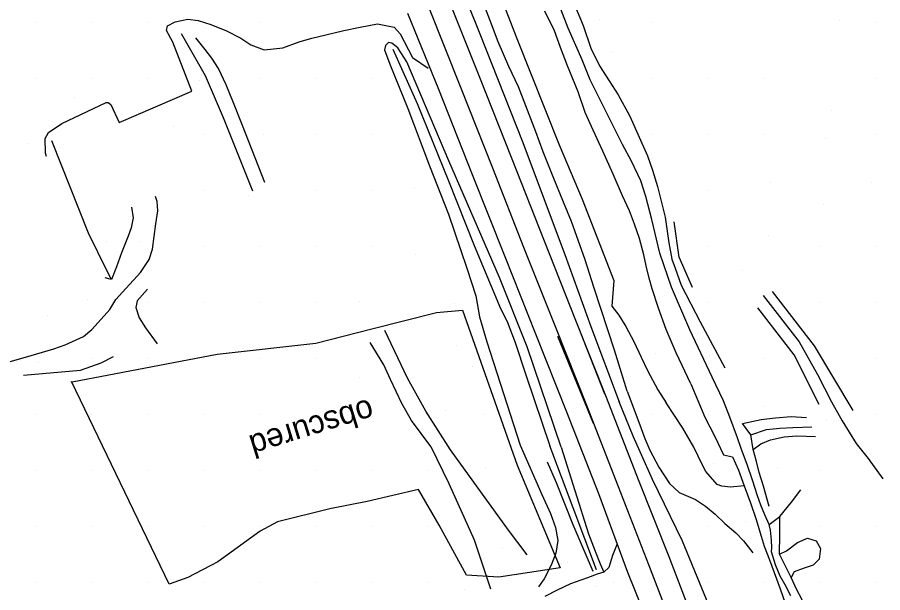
# Model space of a CAD drawing. Extents: x 524772 to 528246, y 273285 to 283088.
# Drawn here: x 527735.4 to 527886.1, y 274221.1 to 274321.4 of the extents above; entities that cross this region are included whole.
import ezdxf

# ---------------------------------------------------------------- set-up
doc = ezdxf.new("R2010")
doc.units = 0
for name, color, linetype in [('Exist DTM Crownline', 7, 'Continuous'), ('Exist Roads EOP', 7, 'Continuous'), ('Exist Roads Soil', 7, 'Continuous'), ('Old_Level_12', 7, 'Continuous'), ('PH Exist DTM Breakline', 7, 'Continuous'), ('PH Exist DTM Point', 7, 'Continuous')]:
    doc.layers.add(name, color=color, linetype=linetype)

msp = doc.modelspace()

# ---------------------------------------------------------------- linework, layer by layer
at = {"layer": 'Exist DTM Crownline'}
msp.add_lwpolyline([(527877.32, 274141.9), (527872.16, 274155.51), (527866.36, 274171.44), (527861.32, 274184.4), (527856.24, 274197.5), (527850.61, 274212.41), (527845.36, 274225.99), (527840.1, 274239.58), (527834.55, 274253.77), (527829.3, 274267.02), (527823.63, 274281.27), (527818.21, 274295.07), (527812.62, 274309.15), (527807.09, 274323.12)], dxfattribs=at)
at = {"layer": 'Exist Roads EOP'}
for points in [[(527863.89, 274191.51), (527862.12, 274195.56), (527861.19, 274196.14), (527859.74, 274198.94), (527854.35, 274213.12), (527848.92, 274227.38), (527843.58, 274240.81), (527838, 274255.12), (527832.68, 274268.57), (527827.21, 274282.4), (527821.56, 274296.66), (527815.92, 274310.87), (527810.35, 274324.86), (527804.78, 274338.91), (527799.29, 274352.72), (527793.54, 274366.95), (527787.87, 274381.23), (527782.28, 274395.33), (527776.62, 274409.52), (527770.97, 274423.52), (527765.47, 274437.47), (527760, 274451.08), (527754.4, 274465.08), (527748.73, 274479.07)], [(527873.92, 274140.45), (527869.86, 274151.18), (527864.48, 274165.61), (527858.1, 274182.62), (527852.91, 274196.02), (527847.38, 274210.53), (527841.71, 274224.63), (527836.64, 274238.36), (527831.12, 274252.6), (527825.69, 274266.18), (527820.35, 274279.64), (527814.69, 274293.96), (527808.82, 274308.77), (527803.4, 274322.05)]]:
    msp.add_lwpolyline(points, dxfattribs=at)
at = {"layer": 'Exist Roads Soil'}
msp.add_lwpolyline([(527795.11, 274319.68), (527798.16, 274320.21), (527801.06, 274319.65), (527802.1, 274318.49), (527804.22, 274314.4), (527806.98, 274312.53)], dxfattribs=at)
at = {"layer": 'Old_Level_12'}
msp.add_lwpolyline([(527744.97, 274257.89), (527770.21, 274262.72), (527787.37, 274264.63), (527797.16, 274267.12), (527808.42, 274269.96), (527812.91, 274270.38), (527822.44, 274243.36), (527829.96, 274225.48), (527819.23, 274223.82), (527813.62, 274224.2), (527808.87, 274232.9), (527805.28, 274239.09), (527796.33, 274237), (527789.84, 274235.75), (527780.73, 274233.46), (527777.7, 274231.87), (527770.34, 274226.52), (527765.09, 274223.76), (527761.87, 274222.62), (527744.86, 274257.95)], dxfattribs=at)
at = {"layer": 'PH Exist DTM Breakline'}
for points in [[(527741.66, 274504.6), (527745.51, 274495.8), (527753.01, 274476.72), (527758.97, 274462.16), (527764.73, 274447.27), (527771.16, 274430.65), (527775.35, 274420.77), (527782.56, 274402.44), (527787.94, 274388.77), (527793.91, 274373.37), (527798.61, 274361.95), (527803.2, 274350.89), (527807.64, 274339.89), (527811.88, 274328.63), (527815.94, 274318.47), (527823.29, 274299.84), (527830.72, 274280.05), (527835.27, 274267.52), (527840.2, 274254.37)], [(527817.96, 274329.14), (527822.29, 274317.95), (527829.76, 274299.14), (527833.77, 274289.68), (527839.3, 274275.51), (527838.92, 274271.05), (527840.12, 274269.5), (527841.36, 274267.51), (527842.74, 274264.87), (527844.03, 274262.16), (527845.16, 274259.85), (527846.91, 274256.5), (527848.38, 274254.19)], [(527841.62, 274256.24), (527839.4, 274263.4), (527837.07, 274270.45), (527835.77, 274274.35), (527834.31, 274279.14), (527831.93, 274285.79), (527830.54, 274289.16), (527828.74, 274293.61), (527826.95, 274297.92), (527825.71, 274301.45), (527823.97, 274305.96), (527822.65, 274309.28), (527820.98, 274312.79), (527819.14, 274317.09), (527817.98, 274320.2), (527816.09, 274325.23)], [(527856.37, 274258.66), (527852.53, 274266.92), (527849.31, 274274.39), (527847.31, 274280.29), (527845.87, 274286.14), (527844.86, 274290.17), (527843.98, 274292.89), (527842.33, 274296.29), (527840.8, 274299.22), (527837.24, 274306.31), (527835.18, 274310.49), (527833.74, 274313.97), (527831.35, 274319.51), (527829.05, 274325.42)], [(527831.57, 274325.69), (527833.96, 274319.92), (527835.25, 274315.99), (527836.76, 274312.92), (527838.48, 274310.3), (527840.01, 274307.86), (527842.06, 274304.17), (527843.44, 274301), (527845.11, 274297.23), (527846.02, 274294.75), (527846.87, 274291.88), (527848.24, 274286.56), (527848.87, 274282.1), (527849.38, 274279.25), (527849.97, 274277.7), (527851.01, 274274.73), (527854.28, 274268.34), (527858.59, 274260.32)], [(527852.67, 274257.52), (527850.13, 274262.91), (527848.36, 274267), (527847.07, 274270.72), (527845.97, 274274.07), (527845.42, 274275.96), (527844.88, 274278.06), (527844.47, 274279.99), (527843.72, 274282.83), (527842.87, 274285.34), (527841.99, 274287.64), (527840.77, 274290.27), (527839.16, 274294.02), (527837.36, 274298.06), (527835.68, 274301.69), (527834.29, 274304.78), (527833.06, 274308.37), (527831.23, 274312.91), (527830.01, 274316.09), (527828.97, 274318.99), (527827.25, 274322.45)], [(527740.51, 274297.14), (527740.31, 274297.71), (527740.3, 274300.29), (527740.88, 274301.31), (527743.18, 274302.88), (527750.9, 274306.53), (527751.27, 274306.53), (527751.71, 274306.19), (527753.14, 274303.06), (527765.82, 274308.49), (527762.48, 274317.05), (527761.42, 274319.05), (527761.58, 274319.91), (527762.93, 274320.6), (527765.13, 274321.07), (527766.89, 274320.84), (527769.14, 274320.15), (527771.84, 274319.03), (527774.35, 274317.74), (527776.08, 274316.59), (527778.41, 274315.71), (527781.68, 274316.08), (527784.5, 274317.11), (527786.7, 274317.72), (527789.14, 274318.34), (527792.3, 274319.05), (527795.11, 274319.68)], [(527763.96, 274318.56), (527768.12, 274311.23), (527771.27, 274303.92), (527776.37, 274291.13)], [(527778.54, 274292.59), (527774.63, 274302.54), (527773.09, 274306.48), (527771.79, 274309.59), (527770.48, 274312.46), (527769.29, 274314.23), (527768.11, 274315.77), (527766.5, 274317.77)], [(527830.08, 274246.48), (527824.16, 274263.97), (527819.35, 274276.05), (527810.56, 274296.35), (527803.24, 274313.59), (527801.69, 274316.03), (527800.61, 274316.89), (527800.04, 274316.97), (527799.53, 274316.48), (527799.37, 274315.71), (527800.29, 274313.19), (527803.4, 274305.47), (527807.18, 274295.48), (527810.49, 274287.06), (527812.59, 274280.95), (527813.71, 274277.7), (527815.23, 274272.88), (527815.91, 274269.2), (527817.15, 274264.86), (527822.97, 274246.85)], [(527800.82, 274315.8), (527805.03, 274306.38), (527810.47, 274292.87), (527814.97, 274281.63), (527819.57, 274270.64), (527820.69, 274268.37), (527821.54, 274266.24), (527822.04, 274264.92), (527823.99, 274258.91), (527828.16, 274246.72)], [(527751.82, 274275.7), (527751.07, 274277.13), (527747.82, 274283.76), (527741.43, 274299.86)], [(527730.67, 274260.45), (527736.87, 274262.17), (527741.78, 274263.62), (527743.77, 274264.3), (527746.94, 274265.78), (527748.43, 274266.98), (527750.05, 274268.76), (527751.52, 274270.45), (527752.56, 274272.21), (527753.75, 274273.51), (527756.85, 274276.9), (527758.39, 274279.17), (527758.99, 274280.99), (527759.55, 274285.41), (527759.88, 274287.64), (527759.76, 274289.29), (527759.5, 274290.14)], [(527755.32, 274288.3), (527755.58, 274286.46), (527755.26, 274284.68), (527754.74, 274283.23), (527753.58, 274280.35), (527752.67, 274277.92), (527751.82, 274275.7), (527750.72, 274276)], [(527852.99, 274274.31), (527850.65, 274279.57), (527849.76, 274285.76)], [(527758.09, 274274.04), (527756.31, 274271.98), (527756.04, 274270.81), (527756.67, 274269.04), (527757.75, 274267.26), (527759.75, 274264.52)], [(527866.86, 274273.62), (527874.14, 274264.12), (527880.87, 274252.88)], [(527865.29, 274272.94), (527871.56, 274264.82), (527874.73, 274259.16), (527877.18, 274254.39), (527879.01, 274251.1), (527881.45, 274247.14), (527883.53, 274244.52), (527886.08, 274240.97)], [(527875.03, 274253.94), (527870.66, 274262.6), (527864.36, 274270.76)], [(527833.19, 274267.14), (527837.66, 274255.81)], [(527810.86, 274246.04), (527806.57, 274252.75), (527803.37, 274258.52), (527799.42, 274266.81)], [(527835.73, 274250.6), (527829.5, 274265.76)], [(527807.42, 274246.62), (527804.04, 274251.15), (527802.39, 274254.07), (527800.4, 274258.25), (527799.22, 274260.82), (527796.84, 274264.71)], [(527736.52, 274259.03), (527746.41, 274259.9), (527750.04, 274261.2), (527752.15, 274262.26)], [(527870.08, 274220.6), (527869.13, 274222.51), (527868.24, 274224.03), (527867.41, 274225.99), (527866.74, 274228.25), (527866.77, 274228.93), (527866.73, 274230.28), (527866.52, 274232.03), (527866.29, 274233.02), (527865.56, 274234.68), (527864.88, 274236.41), (527864.31, 274238.01), (527863.41, 274240.73), (527862.47, 274243.49), (527861.49, 274246.08), (527860.78, 274248.12), (527859.49, 274251.72), (527858.34, 274254.54), (527856.37, 274258.66)], [(527852.67, 274257.52), (527855.13, 274251.71), (527856.84, 274248.33), (527858.38, 274245.18), (527859.91, 274244.8)], [(527841.62, 274256.24), (527843.64, 274250.87), (527844.68, 274248.02), (527845.55, 274245.98), (527847.09, 274242.99), (527848.96, 274240.14), (527850.65, 274238.61), (527853.51, 274237.39), (527855.26, 274236.24), (527856.94, 274234.81), (527858.62, 274233.22), (527860.5, 274231.56), (527861.86, 274230.16), (527863.48, 274228.1)], [(527863.9, 274197.49), (527857.56, 274214.72), (527851.2, 274230.14), (527846, 274240.87), (527842.66, 274248.43), (527840.2, 274254.37)], [(527861.97, 274239.73), (527859.61, 274239.51), (527858.09, 274239.71), (527857.26, 274239.96), (527855.28, 274242.26), (527854.72, 274243.34), (527853.2, 274246.48), (527851.26, 274249.82), (527848.38, 274254.19)], [(527863.12, 274248.63), (527861.66, 274250.61), (527864.92, 274251.32), (527867.44, 274251.62), (527870.16, 274251.83), (527872.8, 274251.64)], [(527863.51, 274246.08), (527863.12, 274248.63), (527865.83, 274249.59), (527868.19, 274249.81), (527870.44, 274249.92), (527873.72, 274250.04)], [(527866.33, 274236.15), (527865.32, 274239.69), (527864.59, 274242.07), (527864.1, 274243.99), (527863.51, 274246.08), (527864.85, 274247.1), (527866.56, 274247.78), (527868.9, 274248.27), (527871.15, 274248.46), (527874.38, 274248.33)], [(527807.42, 274246.62), (527810.54, 274240.15), (527814.99, 274230.32), (527817.79, 274221.83)], [(527824.18, 274227.74), (527820.91, 274232.06), (527810.86, 274246.04)], [(527822.97, 274246.85), (527826.73, 274238.23), (527828.25, 274234.93), (527829.14, 274232.48), (527829.5, 274230.25), (527829.17, 274228.05), (527828.36, 274225.92), (527827.17, 274223.57), (527826.16, 274222.16)], [(527836.26, 274225.14), (527828.16, 274246.72)], [(527830.08, 274246.48), (527834.89, 274231.42), (527836.02, 274228.38), (527836.87, 274226.18), (527837.55, 274224.73)], [(527859.91, 274244.8), (527860.97, 274242.49), (527861.97, 274239.73), (527863.1, 274236.61), (527864.01, 274234.08), (527864.94, 274230.98), (527865.46, 274229.25), (527866.37, 274226.86), (527867.18, 274224.63), (527868.22, 274221.84), (527869.13, 274219.29), (527870.13, 274217.27), (527871.23, 274214.94), (527872.08, 274212.62), (527872.96, 274210.31)], [(527835.66, 274224.85), (527832.18, 274232.94), (527829.27, 274240.29), (527827.75, 274243.89)], [(527866.29, 274233.02), (527868.17, 274234.43), (527870.22, 274236.9), (527871.8, 274239.04)], [(527868.09, 274227.84), (527868.19, 274231.29), (527868.17, 274234.43)], [(527839.84, 274229.67), (527839.04, 274227.64), (527838.38, 274225.52), (527837.55, 274224.73), (527836.39, 274224.35), (527834.7, 274223.75), (527831.75, 274222.67), (527829.4, 274221.58), (527827.28, 274220.45)], [(527870.13, 274223.79), (527868.09, 274227.84), (527869.31, 274228.44), (527871.22, 274229.89), (527872.97, 274230.63), (527874.49, 274230.15), (527875.23, 274228.84), (527875.03, 274227), (527873.95, 274225.92), (527872.25, 274225.34), (527870.67, 274224.76), (527870.13, 274223.79)], [(527877.94, 274180.84), (527876.15, 274181.32), (527874.1, 274181.91), (527872.78, 274182.42), (527871.63, 274182.89), (527870.55, 274183.89), (527870.19, 274184.81), (527870.14, 274185.98), (527870.68, 274188.13), (527871.69, 274190.31), (527872.75, 274193.09), (527874.27, 274196.83), (527875.72, 274200.64), (527876.46, 274202.77), (527876.83, 274204.67), (527876.78, 274207.16), (527876.48, 274208.72), (527875.78, 274211.02), (527874.83, 274213.69), (527873.74, 274216.31), (527872.77, 274218.34), (527871.99, 274220.04), (527871.15, 274221.61), (527870.13, 274223.79)]]:
    msp.add_lwpolyline(points, dxfattribs=at)
at = {"layer": 'PH Exist DTM Point'}
for p, q in [((527738.65, 274320.48), (527738.65, 274320.48)), ((527748.4, 274320.48), (527748.4, 274320.48)), ((527758.16, 274320.48), (527758.16, 274320.48)), ((527777.67, 274320.48), (527777.67, 274320.48)), ((527836.73, 274320.98), (527836.73, 274320.98)), ((527845.94, 274320.48), (527845.94, 274320.48)), ((527878.48, 274320.74), (527878.48, 274320.74)), ((527884.95, 274320.48), (527884.95, 274320.48)), ((527838.93, 274315.31), (527838.93, 274315.31)), ((527738.65, 274310.73), (527738.65, 274310.73)), ((527748.4, 274310.73), (527748.4, 274310.73)), ((527758.16, 274310.73), (527758.16, 274310.73)), ((527767.21, 274310.29), (527767.21, 274310.29)), ((527777.65, 274310.71), (527777.65, 274310.71)), ((527787.42, 274310.73), (527787.42, 274310.73)), ((527797.15, 274310.74), (527797.15, 274310.74)), ((527845.94, 274310.73), (527845.94, 274310.73)), ((527855.7, 274310.71), (527855.7, 274310.71)), ((527865.45, 274310.73), (527865.45, 274310.73)), ((527885.02, 274310.71), (527885.02, 274310.71)), ((527745.43, 274307.32), (527745.43, 274307.32)), ((527877.2, 274305.09), (527877.2, 274305.09)), ((527762.6, 274302.35), (527762.6, 274302.35)), ((527767.91, 274300.98), (527767.91, 274300.98)), ((527778.23, 274300.96), (527778.23, 274300.96)), ((527787.42, 274300.98), (527787.42, 274300.98)), ((527797.17, 274300.98), (527797.17, 274300.98)), ((527845.94, 274300.98), (527845.94, 274300.98)), ((527855.69, 274300.98), (527855.69, 274300.98)), ((527865.45, 274300.98), (527865.45, 274300.98)), ((527884.95, 274300.98), (527884.95, 274300.98)), ((527737.41, 274299.41), (527737.41, 274299.41)), ((527876.15, 274300.2), (527876.15, 274300.2)), ((527767.91, 274291.22), (527767.91, 274291.22)), ((527787.42, 274291.22), (527787.42, 274291.22)), ((527797.17, 274291.22), (527797.17, 274291.22)), ((527804.56, 274291.61), (527804.56, 274291.61)), ((527855.69, 274291.22), (527855.69, 274291.22)), ((527866.6, 274292.62), (527866.6, 274292.62)), ((527884.19, 274292.68), (527884.19, 274292.68)), ((527775.65, 274290.3), (527775.65, 274290.3)), ((527875.74, 274288.78), (527875.74, 274288.78)), ((527750.89, 274282.3), (527750.89, 274282.3)), ((527756.84, 274282.26), (527756.84, 274282.26)), ((527866.16, 274283.43), (527866.16, 274283.43)), ((527767.91, 274281.47), (527767.91, 274281.47)), ((527777.67, 274281.47), (527777.67, 274281.47)), ((527787.42, 274281.47), (527787.42, 274281.47)), ((527797.17, 274281.47), (527797.17, 274281.47)), ((527855.69, 274281.47), (527855.69, 274281.47)), ((527875.2, 274281.47), (527875.2, 274281.47)), ((527884.95, 274281.47), (527884.95, 274281.47)), ((527804.71, 274279.99), (527804.71, 274279.99)), ((527861.64, 274277.26), (527861.64, 274277.26)), ((527747.63, 274272.18), (527747.63, 274272.18)), ((527758.16, 274271.71), (527758.16, 274271.71)), ((527767.91, 274271.71), (527767.91, 274271.71)), ((527777.67, 274271.71), (527777.67, 274271.71)), ((527787.42, 274271.71), (527787.42, 274271.71)), ((527794.98, 274271.85), (527794.98, 274271.85)), ((527855.69, 274271.71), (527855.69, 274271.71)), ((527875.2, 274271.71), (527875.2, 274271.71)), ((527884.95, 274271.71), (527884.95, 274271.71)), ((527811.53, 274271.55), (527811.53, 274271.55)), ((527740.69, 274269.44), (527740.69, 274269.44)), ((527811.9, 274264.14), (527811.9, 274264.14)), ((527846.61, 274262.75), (527846.61, 274262.75)), ((527739.05, 274261.29), (527739.05, 274261.29)), ((527748.4, 274261.96), (527748.4, 274261.96)), ((527758.16, 274261.96), (527758.16, 274261.96)), ((527767.91, 274261.96), (527767.91, 274261.96)), ((527777.67, 274261.96), (527777.67, 274261.96)), ((527787.42, 274261.96), (527787.42, 274261.96)), ((527855.99, 274262.54), (527855.99, 274262.54)), ((527865.45, 274261.96), (527865.45, 274261.96)), ((527884.95, 274261.96), (527884.95, 274261.96)), ((527814.75, 274260.52), (527814.75, 274260.52)), ((527794.99, 274258.69), (527794.99, 274258.69)), ((527865.53, 274253.62), (527865.53, 274253.62)), ((527738.69, 274252.2), (527738.69, 274252.2)), ((527748.4, 274252.21), (527748.4, 274252.21)), ((527758.16, 274252.21), (527758.16, 274252.21)), ((527767.91, 274252.21), (527767.91, 274252.21)), ((527777.67, 274252.21), (527777.67, 274252.21)), ((527787.42, 274252.21), (527787.42, 274252.21)), ((527797.17, 274252.21), (527797.17, 274252.21)), ((527809.96, 274252.88), (527809.96, 274252.88)), ((527816.69, 274252.23), (527816.69, 274252.23)), ((527845.94, 274252.21), (527845.94, 274252.21)), ((527855.69, 274252.21), (527855.69, 274252.21)), ((527884.95, 274252.21), (527884.95, 274252.21)), ((527876.29, 274251.16), (527876.29, 274251.16)), ((527856.64, 274243.69), (527856.64, 274243.69)), ((527738.63, 274242.47), (527738.63, 274242.47)), ((527748.43, 274242.44), (527748.43, 274242.44)), ((527758.16, 274242.45), (527758.16, 274242.45)), ((527767.91, 274242.45), (527767.91, 274242.45)), ((527777.67, 274242.45), (527777.67, 274242.45)), ((527787.42, 274242.45), (527787.42, 274242.45)), ((527797.17, 274242.45), (527797.17, 274242.45)), ((527806.93, 274242.43), (527806.93, 274242.43)), ((527816.87, 274242.94), (527816.87, 274242.94)), ((527867.85, 274242.89), (527867.85, 274242.89)), ((527875.21, 274242.48), (527875.21, 274242.48)), ((527738.67, 274232.69), (527738.67, 274232.69)), ((527748.38, 274232.71), (527748.38, 274232.71)), ((527758.16, 274232.7), (527758.16, 274232.7)), ((527767.91, 274232.7), (527767.91, 274232.7)), ((527777.67, 274232.7), (527777.67, 274232.7)), ((527787.42, 274232.7), (527787.42, 274232.7)), ((527797.17, 274232.7), (527797.17, 274232.7)), ((527806.93, 274232.7), (527806.93, 274232.7)), ((527826.77, 274232.73), (527826.77, 274232.73)), ((527855.69, 274232.7), (527855.69, 274232.7)), ((527862.18, 274233.53), (527862.18, 274233.53)), ((527875.19, 274232.68), (527875.19, 274232.68)), ((527884.95, 274232.7), (527884.95, 274232.7)), ((527819.96, 274228.78), (527819.96, 274228.78)), ((527831.22, 274226.41), (527831.22, 274226.41)), ((527738.65, 274222.95), (527738.65, 274222.95)), ((527748.4, 274222.95), (527748.4, 274222.95)), ((527758.16, 274222.95), (527758.16, 274222.95)), ((527767.91, 274222.95), (527767.91, 274222.95)), ((527777.67, 274222.95), (527777.67, 274222.95)), ((527787.4, 274222.94), (527787.4, 274222.94)), ((527797.17, 274222.97), (527797.17, 274222.97)), ((527806.93, 274222.95), (527806.93, 274222.95)), ((527836.06, 274222.17), (527836.06, 274222.17)), ((527839.19, 274222.95), (527839.19, 274222.95)), ((527855.69, 274222.95), (527855.69, 274222.95)), ((527865.45, 274222.95), (527865.45, 274222.95)), ((527875.2, 274222.95), (527875.2, 274222.95)), ((527884.95, 274222.95), (527884.95, 274222.95)), ((527813.33, 274221.7), (527813.33, 274221.7))]:
    msp.add_line(p, q, dxfattribs=at)

# ---------------------------------------------------------------- texts
at = {"layer": 'Old_Level_12'}
msp.add_text('obscured', height=4.05, rotation=197.2094, dxfattribs=at).set_placement((527796.76, 274254.99))

doc.saveas('drawing.dxf')
